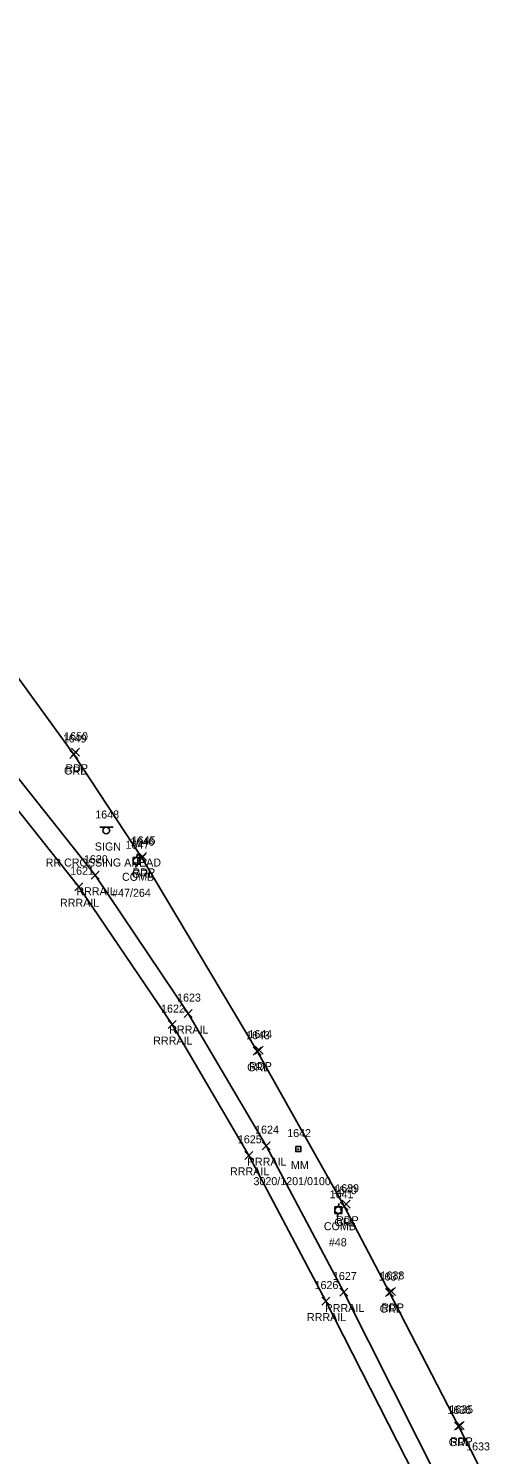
# Model space of a CAD drawing. Extents: x 1635588 to 1637550, y 621583 to 623638.
# Drawn here: x 1636293.9 to 1636409, y 623234.9 to 623591.2 of the extents above; entities that cross this region are included whole.
import ezdxf

# ---------------------------------------------------------------- set-up
doc = ezdxf.new("R2010")
doc.units = 0
for name, color, linetype in [('P_A', 7, 'Continuous'), ('P_I', 7, 'Continuous'), ('P_TIC', 7, 'Continuous'), ('R_A', 7, 'Continuous'), ('R_I', 7, 'Continuous'), ('R_TIC', 7, 'Continuous'), ('RGR', 7, 'Continuous'), ('RR', 7, 'Continuous'), ('S_A', 7, 'Continuous'), ('S_C', 7, 'Continuous'), ('S_I', 7, 'Continuous'), ('SRM', 7, 'Continuous'), ('SSGN', 7, 'Continuous'), ('U_A', 7, 'Continuous'), ('U_C', 7, 'Continuous'), ('U_I', 7, 'Continuous'), ('UP', 7, 'Continuous')]:
    doc.layers.add(name, color=color, linetype=linetype)

msp = doc.modelspace()

# ---------------------------------------------------------------- linework, layer by layer
at = {"layer": 'P_TIC'}
for points in [[(1636304.61, 623409.36), (1636306.61, 623411.36)], [(1636306.61, 623409.36), (1636304.61, 623411.36)], [(1636321.39, 623383.35), (1636323.39, 623385.35)], [(1636323.39, 623383.35), (1636321.39, 623385.35)], [(1636350.54, 623334.93), (1636352.54, 623336.93)], [(1636352.54, 623334.93), (1636350.54, 623336.93)], [(1636372.25, 623296.43), (1636374.25, 623298.43)], [(1636374.25, 623296.43), (1636372.25, 623298.43)], [(1636383.56, 623274.64), (1636385.56, 623276.64)], [(1636385.56, 623274.64), (1636383.56, 623276.64)], [(1636400.73, 623241.19), (1636402.73, 623243.19)], [(1636402.73, 623241.19), (1636400.73, 623243.19)]]:
    msp.add_lwpolyline(points, dxfattribs=at)
at = {"layer": 'R_TIC'}
for points in [[(1636304.19, 623408.8), (1636306.19, 623410.8)], [(1636306.19, 623408.8), (1636304.19, 623410.8)], [(1636321.15, 623383), (1636323.15, 623385)], [(1636323.15, 623383), (1636321.15, 623385)], [(1636309.55, 623378.63), (1636311.55, 623380.63)], [(1636311.55, 623378.63), (1636309.55, 623380.63)], [(1636305.45, 623375.76), (1636307.45, 623377.76)], [(1636307.45, 623375.76), (1636305.45, 623377.76)], [(1636332.74, 623344.07), (1636334.74, 623346.07)], [(1636334.74, 623344.07), (1636332.74, 623346.07)], [(1636328.74, 623341.31), (1636330.74, 623343.31)], [(1636330.74, 623341.31), (1636328.74, 623343.31)], [(1636349.97, 623334.65), (1636351.97, 623336.65)], [(1636351.97, 623334.65), (1636349.97, 623336.65)], [(1636352.23, 623311.06), (1636354.23, 623313.06)], [(1636354.23, 623311.06), (1636352.23, 623313.06)], [(1636347.93, 623308.65), (1636349.93, 623310.65)], [(1636349.93, 623308.65), (1636347.93, 623310.65)], [(1636371.77, 623295.95), (1636373.77, 623297.95)], [(1636373.77, 623295.95), (1636371.77, 623297.95)], [(1636367.15, 623272.24), (1636369.15, 623274.24)], [(1636369.15, 623272.24), (1636367.15, 623274.24)], [(1636371.67, 623274.5), (1636373.67, 623276.5)], [(1636373.67, 623274.5), (1636371.67, 623276.5)], [(1636383.07, 623274.37), (1636385.07, 623276.37)], [(1636385.07, 623274.37), (1636383.07, 623276.37)], [(1636400.32, 623241.01), (1636402.32, 623243.01)], [(1636402.32, 623241.01), (1636400.32, 623243.01)]]:
    msp.add_lwpolyline(points, dxfattribs=at)
at = {"layer": 'RGR'}
msp.add_lwpolyline([(1636408.27, 623221.21), (1636408.36, 623225.15), (1636405.95, 623232.92), (1636401.32, 623242.01), (1636384.07, 623275.37), (1636372.77, 623296.95), (1636350.97, 623335.65), (1636322.15, 623384), (1636305.19, 623409.8), (1636285.27, 623437.15)], dxfattribs=at)
at = {"layer": 'RR'}
for points in [[(1635804.38, 623587.78), (1635886, 623591.18), (1635924.86, 623590.87), (1635951.97, 623589.69), (1635990.42, 623585.12), (1636025.5, 623577.68), (1636061.16, 623567.3), (1636080.11, 623560.16), (1636116.76, 623544.58), (1636140.64, 623532.31), (1636172.21, 623513.66), (1636196.85, 623496.79), (1636223, 623476.01), (1636248.62, 623451.82), (1636277.3, 623421.48), (1636310.55, 623379.63), (1636333.74, 623345.07), (1636353.23, 623312.06), (1636372.67, 623275.5), (1636403.41, 623214.43)], [(1635804.54, 623582.78), (1635886.42, 623586.09), (1635924.26, 623585.89), (1635952.04, 623584.59), (1635989.32, 623580.18), (1636024.35, 623572.88), (1636059.67, 623562.36), (1636078.46, 623555.55), (1636114.37, 623540.19), (1636138.58, 623527.78), (1636169.41, 623509.57), (1636193.73, 623492.88), (1636219.9, 623472.06), (1636245.31, 623448.34), (1636273.58, 623418.05), (1636306.45, 623376.76), (1636329.74, 623342.31), (1636348.93, 623309.65), (1636368.15, 623273.24), (1636399.35, 623212.11)]]:
    msp.add_lwpolyline(points, dxfattribs=at)
at = {"layer": 'SRM'}
msp.add_lwpolyline([(1636360.63, 623311.82), (1636361.88, 623311.82), (1636361.88, 623310.57), (1636360.63, 623310.57)], close=True, dxfattribs=at)
msp.add_circle((1636361.25, 623311.2), 0.0833, dxfattribs=at)
at = {"layer": 'SSGN'}
for p, q in [((1636311.66, 623391.67), (1636315, 623391.67)), ((1636313.31, 623390.83), (1636313.31, 623390.83))]:
    msp.add_line(p, q, dxfattribs=at)
msp.add_circle((1636313.31, 623390.83), 0.833, dxfattribs=at)
at = {"layer": 'UP'}
for p, q in [((1636320.02, 623382.4), (1636320.02, 623384.07)), ((1636320.02, 623384.07), (1636321.68, 623384.07)), ((1636321.1, 623384.9), (1636320.85, 623384.07)), ((1636321.68, 623384.07), (1636321.68, 623382.4)), ((1636321.68, 623382.4), (1636320.02, 623382.4)), ((1636320.6, 623381.57), (1636320.85, 623382.4)), ((1636320.85, 623383.24), (1636320.85, 623383.24)), ((1636370.45, 623295.11), (1636370.45, 623296.78)), ((1636370.45, 623296.78), (1636372.12, 623296.78)), ((1636372.12, 623295.11), (1636370.45, 623295.11)), ((1636371.03, 623294.28), (1636371.28, 623295.11)), ((1636371.53, 623297.61), (1636371.28, 623296.78)), ((1636371.28, 623295.94), (1636371.28, 623295.94)), ((1636372.12, 623296.78), (1636372.12, 623295.11))]:
    msp.add_line(p, q, dxfattribs=at)
for centre in [(1636320.85, 623383.24), (1636371.28, 623295.94)]:
    msp.add_circle(centre, 0.833, dxfattribs=at)

# ---------------------------------------------------------------- texts
at = {"layer": 'P_A'}
for p in [(1636303.1, 623405.36), (1636319.87, 623379.35), (1636349.03, 623330.93), (1636370.74, 623292.43), (1636382.04, 623270.64), (1636399.22, 623237.19)]:
    msp.add_text('RDP', height=2, dxfattribs=at).set_placement(p)
at = {"layer": 'P_I'}
for s, p in [('1650', (1636302.78, 623413.36)), ('1645', (1636319.65, 623387.35)), ('1644', (1636348.8, 623338.93)), ('1639', (1636370.5, 623300.43)), ('1638', (1636381.82, 623278.64)), ('1635', (1636398.99, 623245.19))]:
    msp.add_text(s, height=2, dxfattribs=at).set_placement(p)
at = {"layer": 'R_A'}
for s, p in [('GRL', (1636302.74, 623404.8)), ('GRL', (1636319.69, 623379)), ('RRRAIL', (1636305.84, 623374.63)), ('RRRAIL', (1636301.74, 623371.76)), ('RRRAIL', (1636329.03, 623340.07)), ('RRRAIL', (1636325.03, 623337.31)), ('GRL', (1636348.51, 623330.65)), ('RRRAIL', (1636348.52, 623307.06)), ('RRRAIL', (1636344.22, 623304.65)), ('GRL', (1636370.31, 623291.95)), ('RRRAIL', (1636363.44, 623268.24)), ('RRRAIL', (1636367.96, 623270.5)), ('GRL', (1636381.62, 623270.37)), ('GRL', (1636398.86, 623237.01))]:
    msp.add_text(s, height=2, dxfattribs=at).set_placement(p)
at = {"layer": 'R_I'}
for s, p in [('1649', (1636302.45, 623412.8)), ('1646', (1636319.35, 623387)), ('1620', (1636307.72, 623382.63)), ('1621', (1636304.28, 623379.76)), ('1623', (1636331, 623348.07)), ('1622', (1636327, 623345.31)), ('1643', (1636348.23, 623338.65)), ('1624', (1636350.49, 623315.06)), ('1625', (1636346.19, 623312.65)), ('1640', (1636369.94, 623299.95)), ('1627', (1636369.93, 623278.5)), ('1637', (1636381.34, 623278.37)), ('1626', (1636365.35, 623276.24)), ('1636', (1636398.52, 623245.01)), ('1633', (1636403.22, 623235.92))]:
    msp.add_text(s, height=2, dxfattribs=at).set_placement(p)
at = {"layer": 'S_A'}
for s, p in [('SIGN', (1636310.45, 623385.81)), ('MM', (1636359.44, 623306.2))]:
    msp.add_text(s, height=2, dxfattribs=at).set_placement(p)
at = {"layer": 'S_C'}
for s, p in [('RR CROSSING AHEAD', (1636298.16, 623381.81)), ('3020/1201/0100', (1636350.08, 623302.2))]:
    msp.add_text(s, height=2, dxfattribs=at).set_placement(p)
at = {"layer": 'S_I'}
for s, p in [('1648', (1636310.55, 623393.81)), ('1642', (1636358.51, 623314.2))]:
    msp.add_text(s, height=2, dxfattribs=at).set_placement(p)
at = {"layer": 'U_A'}
for p in [(1636317.23, 623378.24), (1636367.67, 623290.94)]:
    msp.add_text('COMB', height=2, dxfattribs=at).set_placement(p)
at = {"layer": 'U_C'}
for s, p in [('#47/264', (1636314.77, 623374.24)), ('#48', (1636368.92, 623286.94))]:
    msp.add_text(s, height=2, dxfattribs=at).set_placement(p)
at = {"layer": 'U_I'}
for s, p in [('1647', (1636318.11, 623386.24)), ('1641', (1636369.11, 623298.94))]:
    msp.add_text(s, height=2, dxfattribs=at).set_placement(p)

doc.saveas('drawing.dxf')
